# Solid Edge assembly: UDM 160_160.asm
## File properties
Title: Zylinder
Author: ahadarics
Template: iso assembly.asm
Last saved by: ahadarics
Revision: 41
Application: Solid Edge
Username: ahadarics
Dokumentum tartalom típus: 1
Document Number: UDM 160/160
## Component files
Profilrohr 160_160.par
Mutter.par
Kolbenstange 160_160.par
Kit_1.par
Zugstange 160_160.par
Kit_2.par
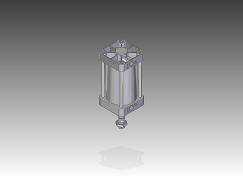
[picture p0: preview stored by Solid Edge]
